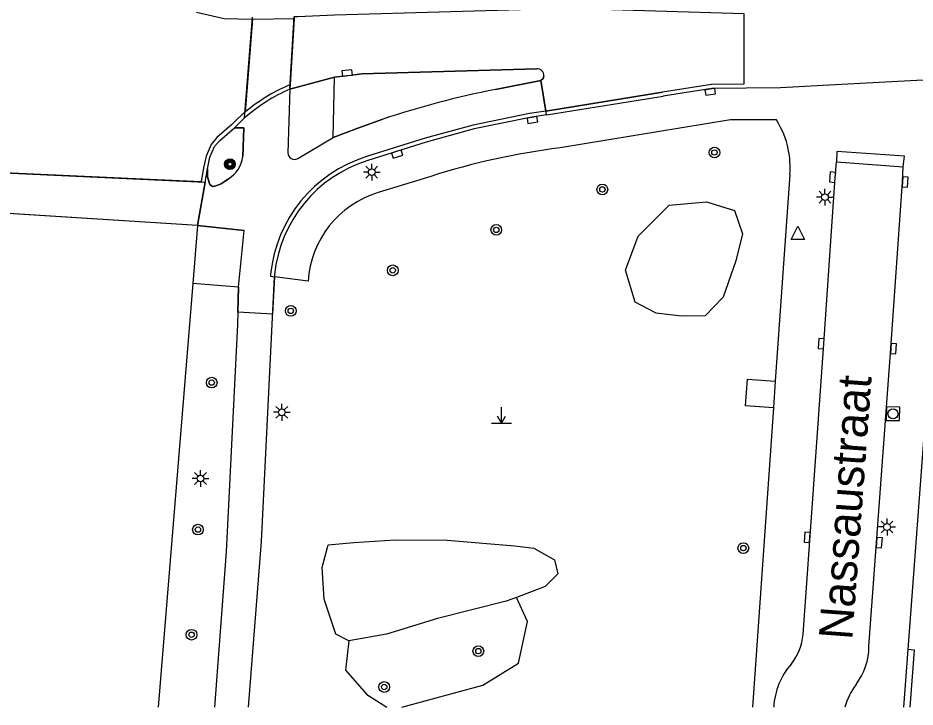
# Model space of a CAD drawing. Extents: x 132573 to 132944, y 398226 to 398676.
# Drawn here: x 132750.7 to 132817.6, y 398226.3 to 398277.6 of the extents above; entities that cross this region are included whole.
import ezdxf

# ---------------------------------------------------------------- set-up
doc = ezdxf.new("R2010")
doc.units = 0
for name, color, linetype in [('gg-anno-openbare ruimte label', 7, 'Continuous'), ('gg-knt-verharding', 7, 'Continuous'), ('gg-knt-verharding nz', 7, 'Continuous'), ('gt-grn-groengrens', 7, 'Continuous'), ('gt-symb-boom', 7, 'Continuous'), ('gt-symb-kolk', 7, 'Continuous'), ('gt-symb-lichtmast', 7, 'Continuous'), ('gt-symb-markant object', 7, 'Continuous'), ('gt-symb-portaalmast', 7, 'Continuous'), ('gt-symb-rioolschacht', 7, 'Continuous'), ('gt-symb-waterafsluiter', 7, 'Continuous'), ('ir-asfa-asfalt arcering', 7, 'Continuous'), ('ir-asfa-asfalt rood', 7, 'Continuous')]:
    doc.layers.add(name, color=color, linetype=linetype)

msp = doc.modelspace()

# ---------------------------------------------------------------- linework, layer by layer
at = {"layer": 'gg-knt-verharding'}
for p, q in [((132827.748, 398273.511), (132817.229, 398272.946)), ((132770.98, 398272.33), (132774.31, 398273.21)), ((132774.21, 398268.72), (132774.31, 398273.21)), ((132789.685, 398272.977), (132786.288, 398272.296)), ((132790.095, 398270.401), (132789.685, 398272.977)), ((132817.229, 398272.946), (132812.085, 398272.669)), ((132770.98, 398272.33), (132770.836, 398267.594)), ((132790.095, 398270.401), (132798.784, 398271.809)), ((132803.807, 398270.031), (132791.12, 398267.95)), ((132807.225, 398270.031), (132803.807, 398270.031)), ((132771.571, 398267.16), (132774.21, 398268.72)), ((132811.742, 398267.692), (132811.709, 398266.91)), ((132816.787, 398267.332), (132811.742, 398267.692)), ((132816.687, 398266.542), (132816.787, 398267.332)), ((132811.709, 398266.91), (132816.687, 398266.542)), ((132764.659, 398265.406), (132764.835, 398266.399)), ((132808.228, 398265.975), (132807.147, 398250.571)), ((132764.659, 398265.406), (132764.086, 398262.163)), ((132781.471, 398265.821), (132777.56, 398264.62)), ((132764.086, 398262.163), (132763.735, 398257.852)), ((132764.086, 398262.163), (132767.582, 398261.805)), ((132767.144, 398257.587), (132767.582, 398261.805)), ((132769.836, 398258.523), (132769.819, 398258.351)), ((132772.34, 398258.012), (132769.819, 398258.351)), ((132763.735, 398257.852), (132761.164, 398226.299)), ((132767.144, 398257.587), (132763.735, 398257.852)), ((132818.966, 398256.451), (132817.017, 398230.579)), ((132807.147, 398250.571), (132807.008, 398248.593)), ((132807.008, 398248.593), (132805.443, 398226.299)), ((132817.017, 398230.579), (132816.694, 398226.299))]:
    msp.add_line(p, q, dxfattribs=at)
for points in [[(132774.31, 398273.21), (132776.35, 398273.47), (132789.37, 398273.84)], [(132789.905, 398273.303), (132789.841, 398273.109), (132789.685, 398272.977)], [(132812.085, 398272.669), (132807.545, 398272.425), (132802.419, 398272.385), (132798.784, 398271.809)], [(132766.839, 398269.453), (132767.217, 398269.829), (132767.607, 398270.186)], [(132777.891, 398270.082), (132776.04, 398269.429), (132774.21, 398268.72)], [(132790.095, 398270.401), (132788.88, 398270.21), (132784.71, 398269.36), (132781.14, 398268.38), (132776.778, 398267.015)], [(132764.835, 398266.399), (132765.023, 398267.248), (132765.366, 398268.048), (132765.751, 398268.504), (132766.839, 398269.453)], [(132766.839, 398269.453), (132767.547, 398269.434), (132767.47, 398267.299)], [(132809.216, 398231.712), (132810.759, 398253.346), (132811.617, 398265.754), (132811.709, 398266.91)], [(132766.397, 398265.636), (132765.852, 398265.281), (132765.45, 398265.113), (132765.207, 398265.086), (132765.009, 398265.23), (132764.838, 398265.802), (132764.835, 398266.399)], [(132814.128, 398230.813), (132815.752, 398253.002), (132816.623, 398265.432), (132816.687, 398266.542)], [(132767.894, 398226.299), (132768.854, 398238.625), (132769.819, 398258.351)], [(132767.144, 398257.587), (132767.086, 398254.813), (132766.237, 398237.869), (132765.349, 398226.299)], [(132807.008, 398248.593), (132804.934, 398248.738), (132805.077, 398250.716), (132807.147, 398250.571)]]:
    msp.add_lwpolyline(points, dxfattribs=at)
for centre, radius, start, end in [((132789.387, 398273.322), 0.518, 357.90391, 91.8823), ((132776.123, 398260.514), 12.887, 113.52071, 131.36231), ((132798.794, 398207.834), 65.664, 100.97936, 108.56216), ((132801.746, 398266.521), 6.507, 11.73249, 32.64514), ((132771.321, 398267.576), 0.485, 177.83747, 301.04086), ((132797.46, 398216.284), 52.054, 96.99635, 107.88893), ((132801.729, 398266.527), 6.523, 355.14695, 11.65066), ((132765.122, 398267.637), 2.373, 302.51878, 351.81943), ((132779.764, 398257.491), 9.981, 107.40584, 174.06387), ((132779.699, 398257.565), 7.372, 106.865, 176.52095), ((132805.118, 398232.066), 4.113, 321.69861, 355.05906), ((132809.447, 398230.828), 4.681, 322.56588, 359.81274), ((132812.314, 398226.017), 5.291, 138.57927, 176.94275), ((132818.006, 398224.505), 5.961, 144.31227, 162.49246)]:
    msp.add_arc(centre, radius, start, end, dxfattribs=at)
at = {"layer": 'gg-knt-verharding nz'}
for p, q in [((132767.607, 398270.186), (132768.2, 398277.68)), ((132771.307, 398277.731), (132770.98, 398272.33)), ((132748.284, 398266.156), (132764.659, 398265.406)), ((132764.086, 398262.163), (132748.157, 398263.181))]:
    msp.add_line(p, q, dxfattribs=at)
at = {"layer": 'gt-grn-groengrens'}
for points in [[(132800.17, 398255.427), (132798.282, 398255.631), (132796.706, 398256.451), (132795.973, 398258.846), (132796.918, 398261.379), (132799.228, 398263.696), (132802.025, 398263.929), (132804.108, 398263.284), (132804.704, 398261.552), (132804.216, 398259.537), (132803.251, 398256.842), (132801.915, 398255.438), (132800.17, 398255.427)], [(132775.371, 398231.219), (132774.407, 398231.723), (132773.531, 398234.325), (132773.371, 398236.695), (132773.819, 398238.392), (132775.754, 398238.568), (132778.832, 398238.766), (132782.69, 398238.739), (132787.731, 398238.309), (132789.156, 398238.131), (132790.697, 398237.272), (132790.947, 398236.21)], [(132790.947, 398236.21), (132789.99, 398235.276), (132787.864, 398234.466)], [(132787.864, 398234.466), (132787.104, 398234.177), (132781.965, 398232.89), (132778.174, 398231.723), (132775.371, 398231.219)], [(132779.315, 398226.299), (132785.358, 398227.925), (132788.014, 398229.566), (132788.683, 398232.676), (132787.864, 398234.466)], [(132775.371, 398231.219), (132775.125, 398229.048), (132776.723, 398227.234), (132778.204, 398226.299)], [(132817.196, 398226.299), (132817.515, 398230.541), (132817.017, 398230.579)]]:
    msp.add_lwpolyline(points, dxfattribs=at)
at = {"layer": 'gt-symb-boom'}
for centre, radius in [((132802.615, 398267.609), 0.4), ((132802.615, 398267.609), 0.2), ((132794.261, 398264.856), 0.4), ((132794.261, 398264.856), 0.2), ((132786.357, 398261.845), 0.4), ((132786.357, 398261.845), 0.2), ((132778.641, 398258.83), 0.4), ((132778.641, 398258.83), 0.2), ((132771.043, 398255.81), 0.4), ((132771.043, 398255.81), 0.2), ((132765.152, 398250.466), 0.4), ((132765.152, 398250.466), 0.2), ((132764.128, 398239.516), 0.4), ((132764.128, 398239.516), 0.2), ((132804.767, 398238.139), 0.4), ((132804.767, 398238.139), 0.2), ((132763.652, 398231.687), 0.4), ((132763.652, 398231.687), 0.2), ((132785.022, 398230.464), 0.4), ((132785.022, 398230.464), 0.2), ((132778.011, 398227.793), 0.4), ((132778.011, 398227.793), 0.2)]:
    msp.add_circle(centre, radius, dxfattribs=at)
at = {"layer": 'gt-symb-kolk'}
for points in [[(132775.262, 398273.331), (132775.634, 398273.377), (132775.585, 398273.774), (132774.841, 398273.682), (132774.89, 398273.285), (132775.262, 398273.331)], [(132802.272, 398272.319), (132801.901, 398272.263), (132801.961, 398271.867), (132802.703, 398271.98), (132802.643, 398272.375), (132802.272, 398272.319)], [(132789.019, 398270.226), (132788.649, 398270.163), (132788.717, 398269.769), (132789.456, 398269.895), (132789.389, 398270.289), (132789.019, 398270.226)], [(132778.905, 398267.681), (132778.547, 398267.569), (132778.667, 398267.187), (132779.383, 398267.412), (132779.263, 398267.793), (132778.905, 398267.681)], [(132811.617, 398265.754), (132811.647, 398266.128), (132811.248, 398266.159), (132811.189, 398265.412), (132811.587, 398265.38), (132811.617, 398265.754)], [(132816.623, 398265.432), (132816.597, 398265.058), (132816.996, 398265.03), (132817.048, 398265.778), (132816.649, 398265.806), (132816.623, 398265.432)], [(132810.763, 398253.345), (132810.789, 398253.719), (132810.39, 398253.747), (132810.338, 398252.998), (132810.737, 398252.971), (132810.763, 398253.345)], [(132815.752, 398253.002), (132815.725, 398252.628), (132816.124, 398252.599), (132816.178, 398253.347), (132815.779, 398253.376), (132815.752, 398253.002)], [(132809.723, 398238.925), (132809.75, 398239.299), (132809.351, 398239.327), (132809.297, 398238.579), (132809.696, 398238.551), (132809.723, 398238.925)], [(132814.697, 398238.563), (132814.67, 398238.189), (132815.069, 398238.16), (132815.123, 398238.908), (132814.724, 398238.937), (132814.697, 398238.563)]]:
    msp.add_lwpolyline(points, dxfattribs=at)
at = {"layer": 'gt-symb-lichtmast'}
for p, q in [((132777.076, 398266.388), (132777.076, 398266.763)), ((132776.826, 398266.138), (132776.451, 398266.138)), ((132776.899, 398266.315), (132776.634, 398266.58)), ((132777.518, 398266.58), (132777.253, 398266.315)), ((132777.326, 398266.138), (132777.701, 398266.138)), ((132776.899, 398265.961), (132776.634, 398265.696)), ((132777.076, 398265.888), (132777.076, 398265.513)), ((132777.253, 398265.961), (132777.518, 398265.696)), ((132810.672, 398264.455), (132810.407, 398264.72)), ((132810.849, 398264.528), (132810.849, 398264.903)), ((132811.026, 398264.455), (132811.291, 398264.72)), ((132810.599, 398264.278), (132810.224, 398264.278)), ((132810.672, 398264.101), (132810.407, 398263.836)), ((132810.849, 398264.028), (132810.849, 398263.653)), ((132811.291, 398263.836), (132811.026, 398264.101)), ((132811.099, 398264.278), (132811.474, 398264.278)), ((132770.203, 398248.431), (132769.938, 398248.696)), ((132770.38, 398248.504), (132770.38, 398248.879)), ((132770.557, 398248.431), (132770.822, 398248.696)), ((132770.13, 398248.254), (132769.755, 398248.254)), ((132770.203, 398248.077), (132769.938, 398247.812)), ((132770.38, 398248.004), (132770.38, 398247.629)), ((132770.822, 398247.812), (132770.557, 398248.077)), ((132770.63, 398248.254), (132771.005, 398248.254)), ((132764.316, 398243.57), (132764.316, 398243.945)), ((132764.066, 398243.32), (132763.691, 398243.32)), ((132764.139, 398243.497), (132763.874, 398243.762)), ((132764.493, 398243.497), (132764.758, 398243.762)), ((132764.566, 398243.32), (132764.941, 398243.32)), ((132764.139, 398243.143), (132763.874, 398242.878)), ((132764.316, 398243.07), (132764.316, 398242.695)), ((132764.758, 398242.878), (132764.493, 398243.143)), ((132815.294, 398239.888), (132815.029, 398240.153)), ((132815.471, 398239.961), (132815.471, 398240.336)), ((132815.648, 398239.888), (132815.913, 398240.153)), ((132815.221, 398239.711), (132814.846, 398239.711)), ((132815.294, 398239.534), (132815.029, 398239.269)), ((132815.471, 398239.461), (132815.471, 398239.086)), ((132815.913, 398239.269), (132815.648, 398239.534)), ((132815.721, 398239.711), (132816.096, 398239.711))]:
    msp.add_line(p, q, dxfattribs=at)
for centre in [(132777.076, 398266.138), (132810.849, 398264.278), (132770.38, 398248.254), (132764.316, 398243.32), (132815.471, 398239.711)]:
    msp.add_circle(centre, 0.25, dxfattribs=at)
at = {"layer": 'gt-symb-markant object'}
for p, q in [((132786.753, 398247.445), (132786.753, 398248.645)), ((132786.753, 398247.445), (132786.453, 398247.965)), ((132786.753, 398247.445), (132787.053, 398247.965)), ((132786.003, 398247.445), (132787.503, 398247.445))]:
    msp.add_line(p, q, dxfattribs=at)
at = {"layer": 'gt-symb-portaalmast'}
for radius in [0.4, 0.33, 0.27, 0.21, 0.15]:
    msp.add_circle((132766.509, 398266.736), radius, dxfattribs=at)
at = {"layer": 'gt-symb-rioolschacht'}
msp.add_lwpolyline([(132815.427, 398248.65), (132815.409, 398247.65), (132816.409, 398247.632), (132816.427, 398248.632)], close=True, dxfattribs=at)
msp.add_circle((132815.918, 398248.141), 0.375, dxfattribs=at)
at = {"layer": 'gt-symb-waterafsluiter'}
for p, q in [((132808.324, 398261.126), (132808.824, 398262.126)), ((132808.824, 398262.126), (132809.324, 398261.126)), ((132809.324, 398261.126), (132808.324, 398261.126))]:
    msp.add_line(p, q, dxfattribs=at)
at = {"layer": 'ir-asfa-asfalt arcering'}
msp.add_line((132790.047, 398270.697), (132798.736, 398272.105), dxfattribs=at)
for points in [[(132764.013, 398278.073), (132766.071, 398277.59), (132768.188, 398277.53), (132767.641, 398270.611)], [(132789.37, 398273.84), (132776.35, 398273.47), (132775.634, 398273.379), (132775.585, 398273.774), (132774.841, 398273.682), (132774.89, 398273.285), (132775.166, 398273.319), (132774.31, 398273.21), (132770.98, 398272.33), (132771.307, 398277.731), (132771.558, 398277.735), (132774.29, 398277.87), (132791.63, 398278.35), (132804.809, 398277.956), (132804.809, 398272.704), (132802.394, 398272.685), (132798.737, 398272.105), (132798.736, 398272.105), (132790.048, 398270.697), (132789.685, 398272.977), (132789.841, 398273.109), (132789.905, 398273.303)], [(132767.641, 398270.611), (132768.188, 398277.53), (132768.196, 398277.53), (132768.202, 398277.53), (132771.298, 398277.581), (132770.999, 398272.645), (132770.903, 398272.62), (132770.86, 398272.605)], [(132767.409, 398270.411), (132767.404, 398270.407), (132767.01, 398270.046), (132766.634, 398269.673), (132765.537, 398268.715), (132765.108, 398268.207), (132764.736, 398267.34), (132764.542, 398266.464), (132764.54, 398266.451), (132764.364, 398265.458), (132764.357, 398265.42), (132748.584, 398266.142), (132748.584, 398266.144), (132748.676, 398268.53), (132748.356, 398272.527), (132748.305, 398272.784), (132748.281, 398272.858)]]:
    msp.add_lwpolyline(points, dxfattribs=at)
msp.add_lwpolyline([(132748.457, 398263.19), (132748.443, 398263.635), (132748.584, 398266.139), (132748.584, 398266.142), (132764.659, 398265.406), (132764.086, 398262.163), (132748.456, 398263.162)], close=True, dxfattribs=at)
for centre, radius, start, end in [((132789.387, 398273.322), 0.518, 357.90391, 91.8823), ((132776.123, 398260.514), 13.187, 113.52071, 130.03363), ((132776.123, 398260.514), 13.187, 130.03363, 131.36231)]:
    msp.add_arc(centre, radius, start, end, dxfattribs=at)
at = {"layer": 'ir-asfa-asfalt rood'}
msp.add_line((132770.98, 398272.33), (132770.836, 398267.594), dxfattribs=at)
for points in [[(132786.288, 398272.296), (132789.685, 398272.977), (132790.048, 398270.697), (132788.827, 398270.505), (132784.64, 398269.652), (132781.055, 398268.668), (132776.688, 398267.301)], [(132767.47, 398267.299), (132767.547, 398269.434), (132766.839, 398269.453), (132767.217, 398269.829), (132767.607, 398270.186)], [(132771.571, 398267.16), (132774.21, 398268.72), (132776.04, 398269.429), (132777.891, 398270.082)], [(132769.538, 398258.554), (132769.524, 398258.385), (132769.819, 398258.351), (132769.682, 398255.555), (132767.105, 398255.72), (132767.144, 398257.587), (132767.582, 398261.805), (132764.086, 398262.163), (132764.659, 398265.406), (132764.835, 398266.399), (132764.838, 398265.802), (132765.009, 398265.23), (132765.207, 398265.086), (132765.45, 398265.113), (132765.852, 398265.281), (132766.397, 398265.636)]]:
    msp.add_lwpolyline(points, dxfattribs=at)
for centre, radius, start, end in [((132776.123, 398260.514), 12.887, 113.52071, 131.36231), ((132798.794, 398207.834), 65.664, 100.97936, 108.56216), ((132771.321, 398267.576), 0.485, 177.83747, 301.04086), ((132765.122, 398267.637), 2.373, 302.51878, 351.81943), ((132779.764, 398257.491), 10.281, 107.40584, 174.06387)]:
    msp.add_arc(centre, radius, start, end, dxfattribs=at)

# ---------------------------------------------------------------- texts
at = {"layer": 'gg-anno-openbare ruimte label'}
msp.add_text('Nassaustraat', height=2.5, rotation=85.8, dxfattribs=at).set_placement((132812.878, 398231.262))

doc.saveas('drawing.dxf')
